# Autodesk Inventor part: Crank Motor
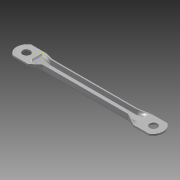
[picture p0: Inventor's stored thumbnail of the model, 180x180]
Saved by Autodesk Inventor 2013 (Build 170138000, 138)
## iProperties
Created: 2006-03
Part Number: Crank Motor
Document SubType Name: Modeling
Designer: Autodesk, Inc.
Material: Stainless Steel, 440C
Mass: 59.5791 g
Surface Area: 96.204 cm^2
Volume: 7.68763 cm^3
Density: 7.75 g/cm^3
Author: Autodesk, Inc.
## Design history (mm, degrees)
sketch "Sketch1"
  geometry: L1 (0, 0)-(0, 1.6); L2 (0, 1.6)-(4.6, 1.6); L3 (4.6, 1.6)-(4.6, 8); L4 (4.6, 8)-(6.2, 8); L5 (6.2, 8)-(6.2, 1.5); L6 (4.7, 0)-(0, 0); L7 (0, 9.662)-(0, -1.973) reference; L8 (-4.6, 1.6)-(-4.6, 8); L9 (-4.6, 8)-(-6.2, 8); L10 (-6.2, 8)-(-6.2, 1.5); L11 (0, 1.6)-(-4.6, 1.6); L12 (-4.7, 0)-(0, 0); A1 r 1.5 centre (4.7, 1.5) between (4.7, 0) and (6.2, 1.5); A2 r 1.5 centre (-4.7, 1.5) between (-6.2, 1.5) and (-4.7, 0)
  constraints: 22 end point, 6 symmetric about line, 4 parallel, 4 point on circle, 2 centre point, 2 perpendicular, 2 tangent, 1 vertical, 1 other
  dimensions: "d1" = 4.6 distance between parallel lines of L3 L1; "d2" = 8 distance between parallel lines of L6 L4; "d3" = 1.6 distance between parallel lines of L5 L3; "d4" = 1.5 radius of A1
extrude "Extrusion1" new body sketch "Sketch1" distance "d5" = 55.6; taper "d6" = 0 deg
workplane "Work Plane1"
sketch "Sketch2"
  geometry: L1 (-1.6, 0)-(9.6, 0) reference; L2 (3, 12)-(5, 12); L3 (5, 12)-(5, -12); L4 (5, -12)-(3, -12); L5 (3, -12)-(3, 12); L6 (3, 12)-(5, -12); L7 (1.5, 6.2)-(8, 6.2) reference; L8 (8, -6.2)-(1.5, -6.2) reference; L9 (0, -4.7)-(0, 4.7) reference; 2 further points
  constraints: 10 end point, 2 midpoint, 2 parallel, 1 horizontal, 1 perpendicular
  dimensions: "d8" = 4 distance from line of point (4, 0) L9; "d9" = 2 distance of L2.start L2.end; "d10" = 24 distance of L2.end L3.end
loft "Loft1" sketch "Sketch2" dims "d11" = 0, "d12" = 90 deg, "d13" = 0, "d14" = 90 deg
  node "Edges1"
sketch "Sketch3"
  geometry: L1 (2, 12.374)-(2, 18.469) reference; L2 (2, 19.993)-(0, 19.993) reference; L3 (2, 18.469)-(2, 19.993) reference; L4 (2, 3.612)-(2, 12.374) reference; L5 (2, -2.483)-(2, 3.612) reference; L6 (2, -4.007)-(2, -2.483) reference; L7 (0, -4.007)-(2, -4.007) reference; L8 (0, 0)-(0, -4.007) reference; L9 (0, 15.986)-(0, 0) reference; L10 (0, 19.993)-(0, 15.986) reference; 1 further point
extrude "Extrusion2" join sketch "Sketch3" distance "d15" = 20; taper "d16" = 0 deg
sketch "Sketch4"
  geometry: L1 (-25.867, 12)-(107.678, 12) reference; L2 (0, 24)-(0, 0); A1 r 14 centre (7.211, 12) between (0, 24) and (0, 0); 1 further point
  constraints: 3 point on circle, 2 end point, 1 centre point, 1 perpendicular, 1 point on line
  dimensions: "d17" = 14 radius of A1
extrude "Extrusion3" join sketch "Sketch4" stored distance "d18" = 20; taper "d19" = 0 deg
sketch "Sketch5"
  geometry: L1 (-45.867, 4.381)-(87.678, 4.381) reference; L2 (0, 12.374)-(0, -3.612) reference; C1 r 5 at (-14, 4.381); 1 further point
  constraints: 1 centre point, 1 point on line
  dimensions: "d20" = 10 diameter of C1; "d21" = 14 distance from line of C1.centre L2
extrude "Extrusion4" cut sketch "Sketch5" stored distance "d22" = 20; taper "d23" = 0 deg
mirror "Mirror1"
body "Solid1"
other parameters: "d7" = 13
